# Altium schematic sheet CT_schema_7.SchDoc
size 251 x 159 mm
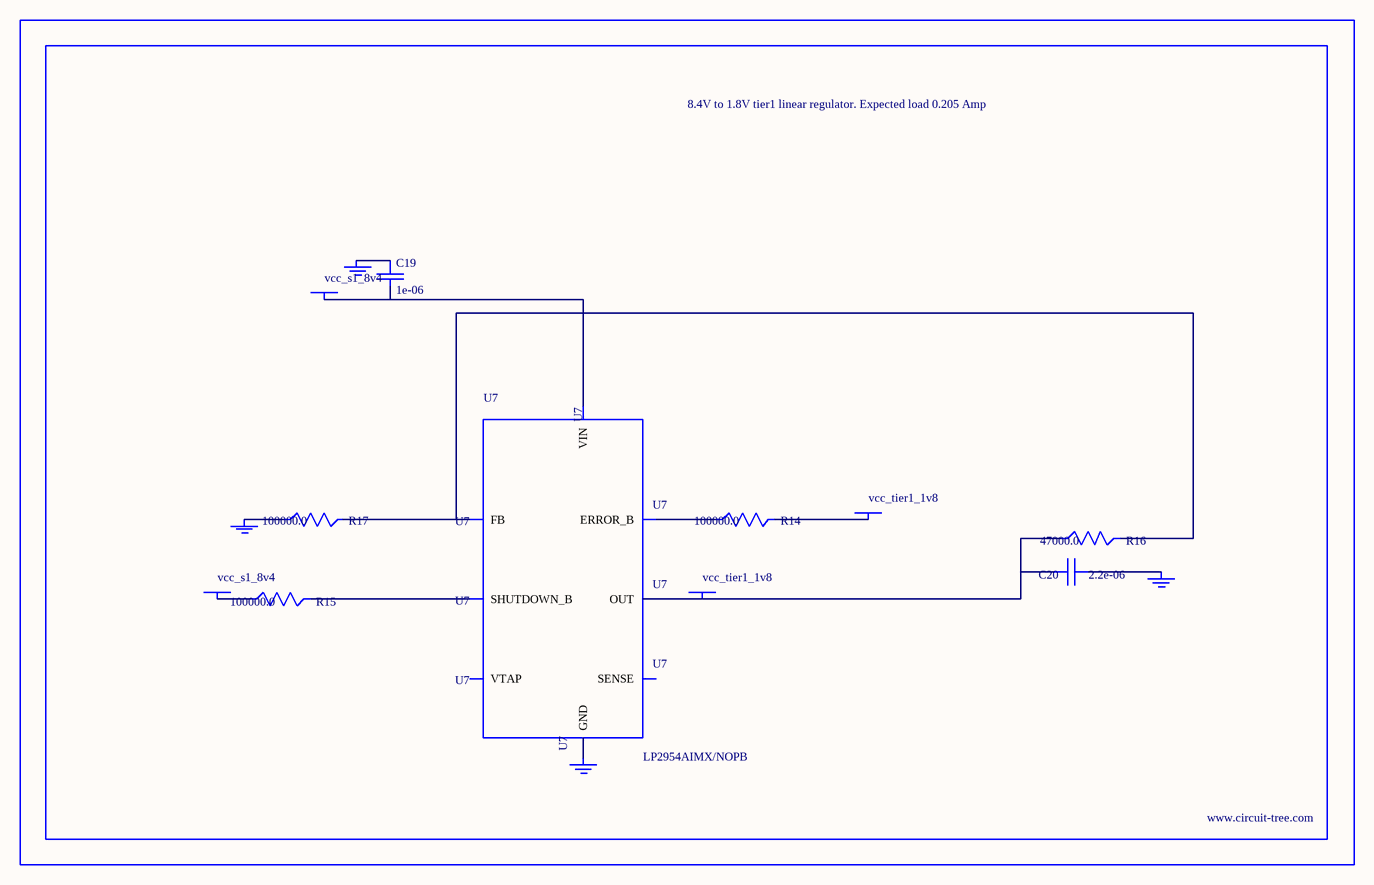
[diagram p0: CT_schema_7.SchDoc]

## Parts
BORDER6  (no value)
C19  1e-06  [EXV-9B]
C20  2.2e-06  [EXV-9B]
GND_INSTANCE_6_0  (no value)
GND_INSTANCE_6_1  (no value)
GND_INSTANCE_6_2  (no value)
GND_INSTANCE_6_3  (no value)
POWER_INSTANCE_6_0  vcc_s1_8v4
POWER_INSTANCE_6_1  vcc_tier1_1v8
POWER_INSTANCE_6_2  vcc_s1_8v4
POWER_INSTANCE_6_3  vcc_tier1_1v8
R14  100000.0  [R0603]
R15  100000.0  [R0603]
R16  47000.0  [R0603]
R17  100000.0  [R0603]
U7  LP2954AIMX/NOPB  [LP2954]

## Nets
NetC19_1: C19.1 GND_INSTANCE_6_2.0(GND)
NetC19_2: C19.2 POWER_INSTANCE_6_2.0(PWR) U7.8(VIN)
NetC20_1: C20.1 GND_INSTANCE_6_0.0(GND)
NetC20_2: C20.2 POWER_INSTANCE_6_3.0(PWR) R16.1 U7.1(OUT)
NetGND_INSTANCE_6_1_0: GND_INSTANCE_6_1.0(GND) R17.1
NetGND_INSTANCE_6_3_0: GND_INSTANCE_6_3.0(GND) U7.4(GND)
NetPOWER_INSTANCE_6_0_0: POWER_INSTANCE_6_0.0(PWR) R15.1
NetPOWER_INSTANCE_6_1_0: POWER_INSTANCE_6_1.0(PWR) R14.2
NetR14_1: R14.1 U7.5(ERROR_B)
NetR15_2: R15.2 U7.3(SHUTDOWN_B)
NetR16_2: R16.2 R17.2 U7.7(FB)

Not connected (* = marked no-connect by the designer): U7 2(SENSE) 6(VTAP)

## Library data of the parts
BORDER6 = BORDER_PAGE6
C19 = EDK105M050A9BAA
C20 = EDK225M050A9BAA
GND_INSTANCE_6_0-GND_INSTANCE_6_3 = GND
POWER_INSTANCE_6_0-POWER_INSTANCE_6_3 = PWR
R14 R15 R17 = RC0603JR-07100KL
R16 = RC0603JR-0747KL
